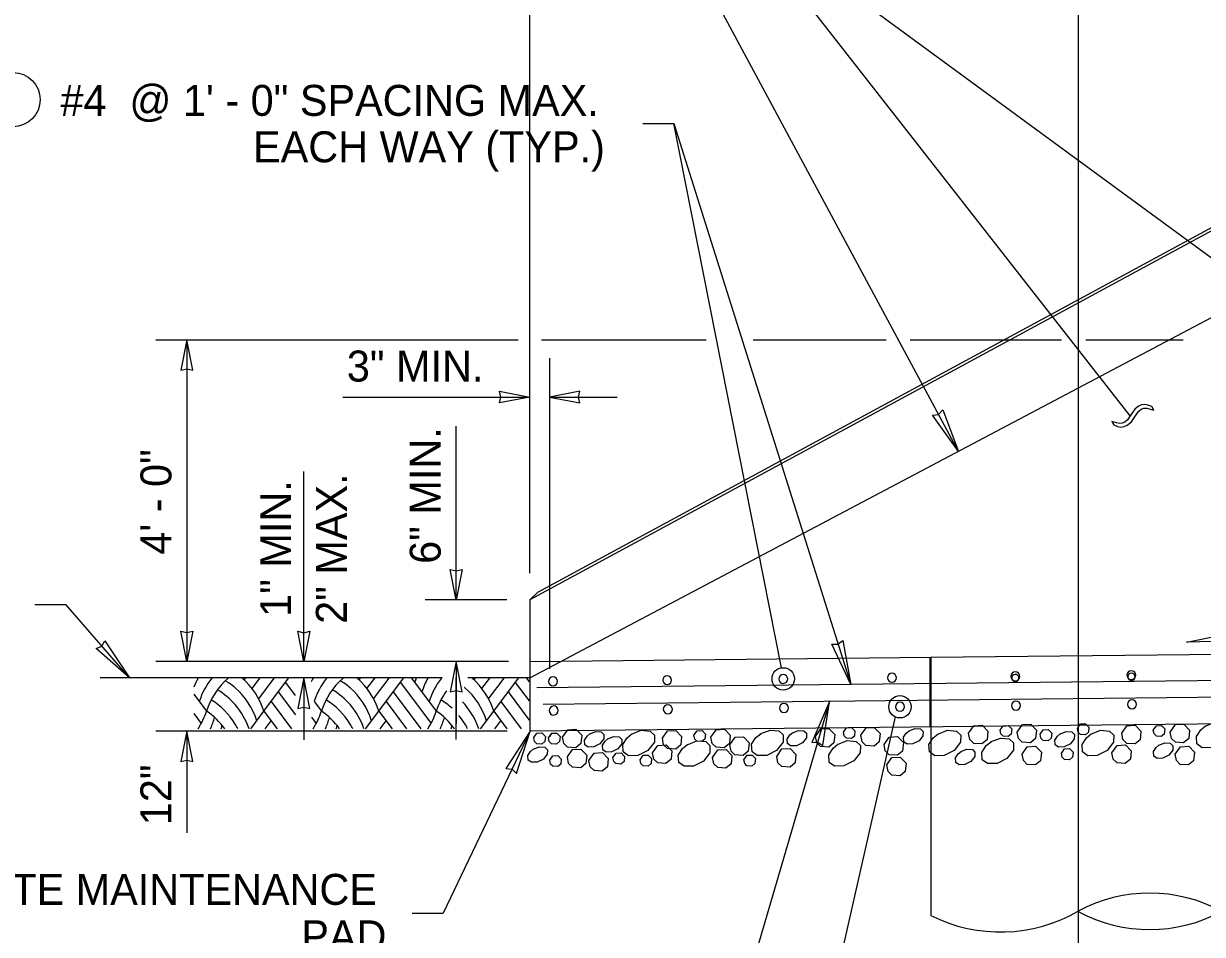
# Model space of a CAD drawing. Extents: x 99862 to 103680, y 99470 to 105076.
# Drawn here: x 101020 to 101629, y 100397 to 100868 of the extents above; entities that cross this region are included whole.
import ezdxf

# ---------------------------------------------------------------- set-up
doc = ezdxf.new("R2010")
doc.units = 0
for name, color, linetype in [('Level 1', 7, 'Continuous'), ('Level 12', 7, 'Continuous'), ('Level 15', 7, 'Continuous'), ('Level 16', 7, 'Continuous'), ('Level 2', 7, 'Continuous'), ('Level 20', 7, 'Continuous'), ('Level 3', 7, 'Continuous'), ('Level 31', 7, 'Continuous'), ('Level 32', 7, 'Continuous'), ('Level 33', 7, 'Continuous'), ('Level 6', 7, 'Continuous')]:
    doc.layers.add(name, color=color, linetype=linetype)

msp = doc.modelspace()

# ---------------------------------------------------------------- linework, layer by layer
at = {"layer": 'Level 1'}
for p in [(101822.22, 100863.19), (101285.51, 100574.36)]:
    msp.add_line(p, (101281.47, 100570.3), dxfattribs=at)
at = {"layer": 'Level 12'}
for p, q in [((101488.78, 100540.75), (101639.12, 100542.36)), ((101281.54, 100502.52), (101281.54, 100538.52)), ((101281.81, 100538.54), (101488.78, 100540.75)), ((101848.46, 100508.36), (101281.54, 100502.52))]:
    msp.add_line(p, q, dxfattribs=at)
at = {"layer": 'Level 15'}
for p, q in [((101281.45, 100747.06), (101281.45, 101114.77)), ((101591.84, 100665.55), (101385.61, 100928.99)), ((101820.5, 100609.84), (101385.61, 100928.99)), ((101565.13, 100284.95), (101565.13, 100883.5)), ((101503.03, 100647.03), (101377.78, 100879.78)), ((101339.87, 100816.5), (101355.87, 100816.5)), ((101355.87, 100816.5), (101447.34, 100526.68)), ((101411.56, 100535.3), (101355.87, 100816.5)), ((101281.45, 100584.16), (101281.45, 100747.06)), ((101088.15, 100704.75), (101275.45, 100704.75)), ((101104.15, 100704.75), (101104.15, 100538.54)), ((101287.45, 100704.75), (101333.49, 100704.75)), ((101333.49, 100704.75), (101372.66, 100704.75)), ((101396.88, 100704.75), (101465.68, 100704.75)), ((101477.99, 100704.75), (101556.24, 100704.75)), ((101568.86, 100704.75), (101619.14, 100704.75)), ((101291.55, 100695.2), (101291.55, 100534.75)), ((101184.7, 100675.2), (101281.45, 100675.2)), ((101291.58, 100675.2), (101326.63, 100675.2)), ((101596.04, 100670.5), (101594.11, 100668.95)), ((101597.57, 100671.14), (101596.04, 100670.5)), ((101599.17, 100671.32), (101597.57, 100671.14)), ((101600.93, 100671.05), (101599.17, 100671.32)), ((101602.95, 100670.3), (101600.93, 100671.05)), ((101604, 100668.47), (101602.95, 100670.3)), ((101591.84, 100665.55), (101590.38, 100663.46)), ((101594.11, 100668.95), (101591.84, 100665.55)), ((101592.38, 100662.31), (101594.9, 100665.93)), ((101594.9, 100665.93), (101596.28, 100667.92)), ((101596.28, 100667.92), (101597.44, 100668.87)), ((101597.44, 100668.87), (101598.78, 100669.35)), ((101598.78, 100669.35), (101600.43, 100669.4)), ((101600.43, 100669.4), (101604, 100668.47)), ((101243.34, 100570.3), (101243.34, 100660.18)), ((101584.62, 100661.83), (101582.31, 100662.57)), ((101582.31, 100662.57), (101583.37, 100660.74)), ((101583.37, 100660.74), (101585.2, 100659.98)), ((101586.33, 100661.56), (101584.62, 100661.83)), ((101585.2, 100659.98), (101586.97, 100659.69)), ((101587.69, 100661.71), (101586.33, 100661.56)), ((101586.97, 100659.69), (101588.67, 100659.88)), ((101588.92, 100662.21), (101587.69, 100661.71)), ((101588.67, 100659.88), (101590.29, 100660.56)), ((101590.38, 100663.46), (101588.92, 100662.21)), ((101590.29, 100660.56), (101592.38, 100662.31)), ((101164.6, 100538.54), (101164.6, 100636.66)), ((101025.57, 100567.91), (101041.57, 100567.91)), ((101074.42, 100529.98), (101041.57, 100567.91)), ((101269.47, 100570.3), (101227.34, 100570.3)), ((101180.08, 100538.54), (101088.15, 100538.54)), ((101270.45, 100538.54), (101180.08, 100538.54)), ((101243.34, 100538.54), (101243.34, 100506.54)), ((101164.6, 100529.98), (101164.6, 100497.98)), ((101243.34, 100498.22), (101243.34, 100530.22)), ((101436.33, 100517.79), (101385.25, 100343.71)), ((101470.26, 100509.87), (101416.69, 100274.32)), ((101269.63, 100502.52), (101088.15, 100502.52)), ((101104.15, 100502.52), (101104.15, 100449.95)), ((101281.54, 100502.52), (101236.61, 100408.46)), ((101220.61, 100408.46), (101236.61, 100408.46))]:
    msp.add_line(p, q, dxfattribs=at)
for points in [[(101104.15, 100704.75), (101101.07, 100689.03), (101104.15, 100689.76), (101107.24, 100689.03)], [(101281.45, 100675.2), (101265.73, 100672.12), (101266.46, 100675.2), (101265.73, 100678.29)], [(101291.58, 100675.2), (101307.31, 100672.12), (101306.58, 100675.2), (101307.31, 100678.29)], [(101503.03, 100647.03), (101489.6, 100665.73), (101492.73, 100666.22), (101494.86, 100668.56)], [(101243.34, 100570.3), (101240.26, 100586.02), (101243.34, 100585.3), (101246.43, 100586.02)], [(101104.15, 100538.54), (101101.07, 100554.26), (101104.15, 100553.53), (101107.24, 100554.26)], [(101164.6, 100538.41), (101161.51, 100554.13), (101164.6, 100553.4), (101167.68, 100554.13)], [(101074.42, 100529.98), (101057.22, 100545.28), (101060.17, 100546.44), (101061.73, 100549.19)], [(101447.34, 100526.68), (101437.55, 100547.52), (101440.72, 100547.42), (101443.24, 100549.34)], [(101243.34, 100538.54), (101240.26, 100522.81), (101243.34, 100523.54), (101246.43, 100522.81)], [(101164.6, 100529.98), (101161.51, 100514.25), (101164.6, 100514.98), (101167.68, 100514.25)], [(101436.34, 100517.8), (101427.17, 100496.68), (101430.33, 100496.88), (101432.91, 100495.04)], [(101104.15, 100502.52), (101101.07, 100486.79), (101104.15, 100487.52), (101107.24, 100486.79)], [(101281.54, 100502.52), (101269.07, 100483.16), (101272.22, 100482.84), (101274.47, 100480.6)]]:
    msp.add_lwpolyline(points, close=True, dxfattribs=at)
for centre in [(101412.42, 100529.51), (101472.76, 100515.09)]:
    msp.add_circle(centre, 5.78, dxfattribs=at)
at = {"layer": 'Level 16'}
for p, q in [((101488.78, 100540.75), (101488.78, 100407.24)), ((101564.9, 100515.67), (101564.9, 100515.67))]:
    msp.add_line(p, q, dxfattribs=at)
for centre, radius, start, end in [((101601.93, 100340.59), 78.19, 61.60047, 118.26803), ((101524.79, 100478.94), 80.23, 243.33243, 300), ((101601.93, 100478.15), 78.19, 241.73197, 298.39953)]:
    msp.add_arc(centre, radius, start, end, dxfattribs=at)
at = {"layer": 'Level 2'}
for p, q in [((101285.51, 100574.36), (101822.13, 100864.83)), ((101281.54, 100538.52), (101281.54, 100570.33))]:
    msp.add_line(p, q, dxfattribs=at)
at = {"layer": 'Level 20'}
msp.add_lwpolyline([(101759.94, 100551.99), (101620.9, 100548.45), (101673.82, 100559.17), (101669.68, 100551.57), (101759.89, 100553.87)], close=True, dxfattribs=at)
msp.add_circle((101014.29, 100828.91), 14, dxfattribs=at)
at = {"layer": 'Level 3'}
msp.add_line((101291.89, 100499.76), (101292.54, 100500.69), dxfattribs=at)
for points in [[(101508.24, 100501.46), (101510.93, 100505.29), (101515.22, 100505.53), (101518.21, 100502.44), (101517.77, 100498.1), (101515.12, 100495.9), (101510.88, 100496.2), (101508.89, 100498.14), (101508.24, 100501.46)], [(101524.55, 100503.04), (101526.17, 100505.33), (101528.74, 100505.48), (101530.54, 100503.62), (101530.28, 100501.02), (101528.69, 100499.7), (101526.14, 100499.88), (101524.94, 100501.04), (101524.56, 100503.03)], [(101533.37, 100502.04), (101536.06, 100505.87), (101540.35, 100506.11), (101543.33, 100503.02), (101542.9, 100498.68), (101540.25, 100496.48), (101536.01, 100496.78), (101534.02, 100498.72), (101533.37, 100502.04)], [(101564.49, 100503.92), (101566.1, 100506.21), (101568.68, 100506.36), (101570.47, 100504.5), (101570.21, 100501.9), (101568.62, 100500.58), (101566.07, 100500.76), (101564.88, 100501.92), (101564.49, 100503.92)], [(101587.39, 100501.46), (101590.08, 100505.29), (101594.37, 100505.53), (101597.35, 100502.44), (101596.92, 100498.1), (101594.27, 100495.9), (101590.03, 100496.2), (101588.04, 100498.14), (101587.39, 100501.46)], [(101603.7, 100503.04), (101605.32, 100505.33), (101607.89, 100505.48), (101609.68, 100503.62), (101609.42, 100501.02), (101607.83, 100499.7), (101605.29, 100499.88), (101604.09, 100501.04), (101603.7, 100503.03)], [(101612.52, 100502.04), (101615.2, 100505.87), (101619.5, 100506.11), (101622.48, 100503.02), (101622.05, 100498.68), (101619.4, 100496.48), (101615.16, 100496.78), (101613.16, 100498.72), (101612.52, 100502.04)], [(101630.56, 100505.1), (101635.59, 100507.1), (101640.21, 100506.7), (101642.41, 100504.61), (101642.34, 100500.86), (101639.01, 100496.6), (101633.85, 100494.02), (101629, 100493.94), (101626.27, 100495.88), (101626.01, 100499.75), (101628.22, 100503.21), (101630.76, 100505.23)], [(101283.51, 100499.16), (101285.13, 100501.45), (101287.7, 100501.6), (101289.5, 100499.74), (101289.24, 100497.14), (101287.65, 100495.82), (101285.1, 100496), (101283.9, 100497.16), (101283.52, 100499.16)], [(101291.12, 100499.09), (101292.73, 100501.39), (101295.31, 100501.53), (101297.1, 100499.68), (101296.84, 100497.08), (101295.25, 100495.75), (101292.71, 100495.94), (101291.51, 100497.1), (101291.12, 100499.09)], [(101298.3, 100499.42), (101300.99, 100503.24), (101305.28, 100503.49), (101308.26, 100500.39), (101307.83, 100496.06), (101305.18, 100493.85), (101300.94, 100494.16), (101298.95, 100496.09), (101298.3, 100499.42)], [(101312.47, 100501.14), (101315.54, 100502.36), (101318.37, 100502.11), (101319.71, 100500.84), (101319.67, 100498.54), (101317.63, 100495.94), (101314.48, 100494.36), (101311.51, 100494.31), (101309.84, 100495.5), (101309.68, 100497.86), (101311.04, 100499.98), (101312.59, 100501.22)], [(101321.76, 100498.54), (101324.84, 100499.76), (101327.66, 100499.51), (101329, 100498.23), (101328.96, 100495.94), (101326.92, 100493.34), (101323.77, 100491.76), (101320.81, 100491.71), (101319.13, 100492.9), (101318.98, 100495.26), (101320.33, 100497.38), (101321.88, 100498.62)], [(101334.01, 100500.97), (101339.04, 100502.97), (101343.66, 100502.57), (101345.86, 100500.48), (101345.79, 100496.73), (101342.45, 100492.47), (101337.3, 100489.89), (101332.45, 100489.81), (101329.72, 100491.75), (101329.46, 100495.62), (101331.67, 100499.08), (101334.21, 100501.1)], [(101349.94, 100498.83), (101352.63, 100502.66), (101356.92, 100502.91), (101359.91, 100499.81), (101359.48, 100495.47), (101356.83, 100493.27), (101352.59, 100493.58), (101350.59, 100495.51), (101349.94, 100498.83)], [(101366.26, 100500.41), (101367.87, 100502.7), (101370.45, 100502.85), (101372.24, 100500.99), (101371.98, 100498.39), (101370.39, 100497.07), (101367.84, 100497.25), (101366.65, 100498.41), (101366.26, 100500.41)], [(101375.07, 100499.42), (101377.76, 100503.24), (101382.05, 100503.49), (101385.04, 100500.39), (101384.61, 100496.06), (101381.95, 100493.85), (101377.72, 100494.16), (101375.72, 100496.09), (101375.07, 100499.42)], [(101384.83, 100495.48), (101387.52, 100499.31), (101391.81, 100499.55), (101394.8, 100496.46), (101394.36, 100492.12), (101391.71, 100489.91), (101387.47, 100490.22), (101385.48, 100492.16), (101384.83, 100495.48)], [(101400.57, 100501.07), (101405.61, 100503.06), (101410.23, 100502.67), (101412.42, 100500.58), (101412.35, 100496.83), (101409.02, 100492.57), (101403.87, 100489.99), (101399.01, 100489.91), (101396.28, 100491.85), (101396.02, 100495.71), (101398.24, 100499.17), (101400.78, 100501.2)], [(101417.21, 100501.7), (101420.29, 100502.92), (101423.11, 100502.68), (101424.46, 100501.4), (101424.41, 100499.11), (101422.37, 100496.5), (101419.23, 100494.93), (101416.26, 100494.88), (101414.59, 100496.06), (101414.43, 100498.43), (101415.78, 100500.54), (101417.34, 100501.78)], [(101429.09, 100499.8), (101431.78, 100503.63), (101436.07, 100503.87), (101439.06, 100500.78), (101438.63, 100496.44), (101435.97, 100494.23), (101431.73, 100494.54), (101429.74, 100496.48), (101429.09, 100499.8)], [(101443.51, 100502), (101445.12, 100504.29), (101447.7, 100504.44), (101449.49, 100502.58), (101449.23, 100499.98), (101447.64, 100498.66), (101445.09, 100498.84), (101443.9, 100500), (101443.51, 100502)], [(101452.53, 100500.36), (101455.22, 100504.19), (101459.51, 100504.43), (101462.49, 100501.34), (101462.06, 100497), (101459.41, 100494.8), (101455.17, 100495.1), (101453.18, 100497.04), (101452.53, 100500.36)], [(101464.54, 100495.59), (101467.23, 100499.42), (101471.53, 100499.66), (101474.51, 100496.57), (101474.08, 100492.23), (101471.43, 100490.03), (101467.19, 100490.33), (101465.19, 100492.27), (101464.55, 100495.59)], [(101477.45, 100502.66), (101480.52, 100503.88), (101483.35, 100503.64), (101484.69, 100502.36), (101484.65, 100500.07), (101482.61, 100497.46), (101479.46, 100495.89), (101476.49, 100495.84), (101474.82, 100497.03), (101474.66, 100499.39), (101476.02, 100501.51), (101477.57, 100502.74)], [(101492.31, 100500.97), (101497.34, 100502.97), (101501.96, 100502.57), (101504.15, 100500.48), (101504.08, 100496.73), (101500.75, 100492.47), (101495.6, 100489.89), (101490.74, 100489.81), (101488.01, 100491.75), (101487.75, 100495.62), (101489.97, 100499.08), (101492.51, 100501.1)], [(101545.23, 100500.88), (101546.84, 100503.18), (101549.42, 100503.32), (101551.21, 100501.47), (101550.95, 100498.86), (101549.36, 100497.54), (101546.81, 100497.72), (101545.62, 100498.89), (101545.23, 100500.88)], [(101555.68, 100501.14), (101558.76, 100502.36), (101561.59, 100502.11), (101562.93, 100500.84), (101562.89, 100498.54), (101560.85, 100495.94), (101557.7, 100494.36), (101554.73, 100494.31), (101553.06, 100495.5), (101552.9, 100497.86), (101554.26, 100499.98), (101555.81, 100501.22)], [(101571.45, 100500.97), (101576.48, 100502.97), (101581.11, 100502.57), (101583.3, 100500.48), (101583.23, 100496.73), (101579.9, 100492.47), (101574.75, 100489.89), (101569.89, 100489.81), (101567.16, 100491.75), (101566.9, 100495.62), (101569.12, 100499.08), (101571.66, 100501.1)], [(101283.27, 100493.22), (101286.34, 100494.44), (101289.17, 100494.2), (101290.51, 100492.92), (101290.47, 100490.63), (101288.43, 100488.02), (101285.28, 100486.45), (101282.31, 100486.4), (101280.64, 100487.58), (101280.48, 100489.95), (101281.84, 100492.06), (101283.39, 100493.3)], [(101300.85, 100489.15), (101303.54, 100492.98), (101307.83, 100493.22), (101310.82, 100490.13), (101310.39, 100485.79), (101307.73, 100483.59), (101303.5, 100483.89), (101301.5, 100485.83), (101300.85, 100489.15)], [(101344.88, 100491.34), (101347.57, 100495.17), (101351.86, 100495.41), (101354.85, 100492.32), (101354.42, 100487.98), (101351.77, 100485.78), (101347.53, 100486.08), (101345.53, 100488.02), (101344.88, 100491.34)], [(101362.69, 100495.5), (101367.72, 100497.5), (101372.35, 100497.1), (101374.54, 100495.01), (101374.47, 100491.26), (101371.14, 100487), (101365.99, 100484.42), (101361.13, 100484.34), (101358.4, 100486.28), (101358.14, 100490.15), (101360.36, 100493.61), (101362.9, 100495.63)], [(101409.05, 100489.45), (101411.73, 100493.28), (101416.03, 100493.52), (101419.01, 100490.43), (101418.58, 100486.09), (101415.93, 100483.89), (101411.69, 100484.19), (101409.7, 100486.13), (101409.05, 100489.45)], [(101440.49, 100495.59), (101445.52, 100497.59), (101450.14, 100497.19), (101452.34, 100495.1), (101452.27, 100491.35), (101448.93, 100487.09), (101443.78, 100484.51), (101438.93, 100484.43), (101436.19, 100486.37), (101435.93, 100490.24), (101438.15, 100493.69), (101440.69, 100495.72)], [(101504.28, 100491.99), (101507.36, 100493.21), (101510.18, 100492.97), (101511.53, 100491.69), (101511.48, 100489.4), (101509.44, 100486.79), (101506.3, 100485.22), (101503.33, 100485.16), (101501.66, 100486.35), (101501.5, 100488.72), (101502.85, 100490.83), (101504.41, 100492.07)], [(101519.64, 100496.91), (101524.67, 100498.9), (101529.29, 100498.5), (101531.48, 100496.41), (101531.41, 100492.66), (101528.08, 100488.4), (101522.93, 100485.83), (101518.07, 100485.74), (101515.34, 100487.68), (101515.08, 100491.55), (101517.3, 100495.01), (101519.84, 100497.03)], [(101535.9, 100490.59), (101538.59, 100494.42), (101542.88, 100494.66), (101545.86, 100491.57), (101545.43, 100487.23), (101542.78, 100485.03), (101538.54, 100485.33), (101536.55, 100487.27), (101535.9, 100490.59)], [(101556.28, 100491.02), (101557.9, 100493.31), (101560.47, 100493.46), (101562.27, 100491.6), (101562.01, 100489), (101560.42, 100487.68), (101557.87, 100487.86), (101556.67, 100489.02), (101556.29, 100491.02)], [(101582.33, 100491.34), (101585.02, 100495.17), (101589.31, 100495.41), (101592.29, 100492.32), (101591.86, 100487.98), (101589.21, 100485.78), (101584.97, 100486.08), (101582.98, 100488.02), (101582.33, 100491.34)], [(101606.6, 100495.27), (101609.67, 100496.49), (101612.5, 100496.25), (101613.84, 100494.97), (101613.8, 100492.68), (101611.76, 100490.07), (101608.61, 100488.5), (101605.64, 100488.45), (101603.97, 100489.63), (101603.81, 100492), (101605.17, 100494.11), (101606.72, 100495.35)], [(101615.05, 100490.59), (101617.73, 100494.42), (101622.03, 100494.66), (101625.01, 100491.57), (101624.58, 100487.23), (101621.93, 100485.03), (101617.69, 100485.33), (101615.7, 100487.27), (101615.05, 100490.59)], [(101291.69, 100487.49), (101293.31, 100489.78), (101295.88, 100489.93), (101297.67, 100488.07), (101297.41, 100485.47), (101295.82, 100484.15), (101293.28, 100484.33), (101292.08, 100485.49), (101291.69, 100487.48)], [(101311.96, 100487.35), (101314.65, 100491.17), (101318.94, 100491.42), (101321.93, 100488.32), (101321.5, 100483.99), (101318.84, 100481.78), (101314.61, 100482.09), (101312.61, 100484.02), (101311.96, 100487.35)], [(101324.38, 100488.86), (101326, 100491.16), (101328.57, 100491.3), (101330.36, 100489.45), (101330.11, 100486.84), (101328.51, 100485.52), (101325.97, 100485.7), (101324.77, 100486.87), (101324.39, 100488.86)], [(101338.42, 100487.71), (101340.04, 100490.01), (101342.61, 100490.16), (101344.4, 100488.3), (101344.14, 100485.7), (101342.55, 100484.37), (101340.01, 100484.56), (101338.81, 100485.72), (101338.42, 100487.71)], [(101375.9, 100488.97), (101378.59, 100492.8), (101382.88, 100493.04), (101385.87, 100489.95), (101385.44, 100485.61), (101382.78, 100483.41), (101378.55, 100483.71), (101376.55, 100485.65), (101375.9, 100488.97)], [(101392.1, 100487.71), (101393.71, 100490.01), (101396.29, 100490.16), (101398.08, 100488.3), (101397.82, 100485.7), (101396.23, 100484.37), (101393.69, 100484.56), (101392.49, 100485.72), (101392.1, 100487.71)], [(101465.95, 100485.03), (101468.64, 100488.85), (101472.93, 100489.1), (101475.91, 100486), (101475.48, 100481.67), (101472.83, 100479.46), (101468.59, 100479.77), (101466.6, 100481.7), (101465.95, 100485.02)]]:
    msp.add_lwpolyline(points, dxfattribs=at)
at = {"layer": 'Level 31'}
for centre, start, end in [((101532.76, 100515.73), 90.61251, 270.61251), ((101532.76, 100515.73), 270.61251, 90.61251), ((101592.75, 100516.37), 90.61251, 270.61251), ((101592.75, 100516.37), 270.61251, 90.61251), ((101293.76, 100513.17), 90.61251, 270.61251), ((101293.76, 100513.17), 270.61251, 90.61251), ((101352.77, 100513.81), 90.61251, 270.61251), ((101352.77, 100513.81), 270.61251, 90.61251), ((101412.76, 100514.45), 90.61251, 270.61251), ((101412.76, 100514.45), 270.61251, 90.61251), ((101472.76, 100515.09), 90.61251, 270.61251), ((101472.76, 100515.09), 270.61251, 90.61251)]:
    msp.add_arc(centre, 2.34, start, end, dxfattribs=at)
at = {"layer": 'Level 32'}
msp.add_line((101829.61, 100522), (101288.39, 100516.21), dxfattribs=at)
at = {"layer": 'Level 33'}
for p, q in [((101488.28, 100540.64), (101488.28, 100504.68)), ((101826.21, 100530.61), (101284.99, 100524.82))]:
    msp.add_line(p, q, dxfattribs=at)
for centre, radius, start, end in [((101293.42, 100528.23), 2.3, 90.61251, 270.61251), ((101293.42, 100528.23), 2.3, 270.61251, 90.61251), ((101352.42, 100528.87), 2.3, 90.61251, 270.61251), ((101352.42, 100528.87), 2.3, 270.61251, 90.61251), ((101412.42, 100529.51), 2.3, 90.61251, 270.61251), ((101412.42, 100529.51), 2.3, 270.61251, 90.61251), ((101468.6, 100530.15), 2.3, 90.61251, 270.61251), ((101468.6, 100530.15), 2.3, 270.61251, 90.61251), ((101532.41, 100530.8), 2.3, 90.61251, 270.61251), ((101532.41, 100529.97), 1.88, 90.61251, 270.61251), ((101532.41, 100530.8), 2.3, 270.61251, 90.61251), ((101532.41, 100529.97), 1.88, 270.61251, 90.61251), ((101592.41, 100531.44), 2.3, 90.61251, 270.61251), ((101592.41, 100530.61), 1.88, 90.61251, 270.61251), ((101592.41, 100531.44), 2.3, 270.61251, 90.61251), ((101592.41, 100530.61), 1.88, 270.61251, 90.61251)]:
    msp.add_arc(centre, radius, start, end, dxfattribs=at)
at = {"layer": 'Level 6'}
for p, q in [((101848.36, 100829.62), (101281.64, 100529.98)), ((101236.16, 100529.98), (101059.35, 100529.98)), ((101133.78, 100528.97), (101134.46, 100529.87)), ((101137.85, 100524.5), (101141.88, 100529.87)), ((101141.3, 100519.2), (101149.31, 100529.87)), ((101143.97, 100512.86), (101156.73, 100529.87)), ((101193.17, 100528.97), (101193.85, 100529.87)), ((101197.25, 100524.5), (101201.28, 100529.87)), ((101200.7, 100519.2), (101208.7, 100529.87)), ((101203.37, 100512.86), (101216.13, 100529.87)), ((101220.31, 100529.87), (101233.07, 100512.86)), ((101281.64, 100529.98), (101249.34, 100529.98)), ((101252.57, 100528.97), (101253.25, 100529.87)), ((101256.65, 100524.5), (101260.68, 100529.87)), ((101260.09, 100519.2), (101268.1, 100529.87)), ((101262.77, 100512.86), (101275.53, 100529.87)), ((101279.71, 100529.87), (101281.11, 100528)), ((101155.11, 100527.71), (101160.14, 100521)), ((101214.51, 100527.71), (101230.39, 100506.53)), ((101273.9, 100527.71), (101281.11, 100518.1)), ((101107.73, 100521.58), (101114.27, 100512.86)), ((101147.68, 100517.81), (101158.22, 100503.77)), ((101151.4, 100522.76), (101160.25, 100510.96)), ((101169.93, 100517.85), (101173.67, 100512.86)), ((101207.08, 100517.81), (101217.61, 100503.77)), ((101210.79, 100522.76), (101225.04, 100503.77)), ((101266.48, 100517.81), (101277.01, 100503.77)), ((101270.19, 100522.76), (101281.11, 100508.2)), ((101107.73, 100511.68), (101111.6, 100506.53)), ((101137.15, 100503.77), (101143.97, 100512.86)), ((101143.97, 100512.86), (101150.79, 100503.77)), ((101196.55, 100503.77), (101203.37, 100512.86)), ((101203.37, 100512.86), (101210.19, 100503.77)), ((101255.95, 100503.77), (101262.77, 100512.86)), ((101262.77, 100512.86), (101269.58, 100503.77)), ((101144.58, 100503.77), (101147.68, 100507.91)), ((101168.65, 100509.66), (101171, 100506.53)), ((101203.98, 100503.77), (101207.08, 100507.91)), ((101263.37, 100503.77), (101266.48, 100507.91))]:
    msp.add_line(p, q, dxfattribs=at)
for centre, start, end in [((101142.66, 100511.37), 150.50505, 158.34455), ((101146.37, 100506.42), 141.38617, 162.3566), ((101150.08, 100501.47), 130.9056, 162.3566), ((101108.16, 100501.47), 17.6434, 49.0944), ((101202.06, 100511.37), 150.50505, 153.4805), ((101205.77, 100506.42), 141.38617, 162.3566), ((101209.48, 100501.47), 130.9056, 162.3566), ((101167.56, 100501.47), 17.6434, 49.0944), ((101257.74, 100516.32), 158.86138, 162.3566), ((101261.45, 100511.37), 150.50505, 162.3566), ((101265.17, 100506.42), 141.38617, 162.3566), ((101226.96, 100501.47), 17.6434, 49.0944), ((101100.74, 100491.57), 40.94134, 59.30215), ((101104.45, 100496.52), 48.95968, 58.54646), ((101104.45, 100496.52), 17.6434, 48.95975), ((101160.14, 100491.57), 40.94134, 59.30215), ((101163.85, 100496.52), 48.95968, 58.54646), ((101163.85, 100496.52), 17.6434, 48.95975), ((101223.24, 100496.52), 48.95968, 49.55103), ((101223.24, 100496.52), 17.6434, 48.95975), ((101097.03, 100486.62), 31.33163, 58.48737), ((101156.42, 100486.62), 31.33163, 58.48737), ((101268.88, 100501.47), 144.34512, 162.3566), ((101215.82, 100486.62), 47.44053, 58.48737), ((101219.53, 100491.57), 40.94134, 43.82968), ((101078.46, 100524.25), 326.97404, 342.3566), ((101093.31, 100481.67), 36.01876, 56.09639), ((101100.74, 100491.57), 18.9418, 40.94141), ((101137.86, 100524.25), 326.97404, 342.3566), ((101152.71, 100481.67), 36.01876, 56.09639), ((101160.14, 100491.57), 18.9418, 40.94141), ((101197.26, 100524.25), 326.97404, 342.3566), ((101212.11, 100481.67), 36.01876, 56.09639), ((101219.53, 100491.57), 18.9418, 40.94141), ((101082.18, 100519.3), 335.58785, 345.01126), ((101085.89, 100514.35), 343.6457, 346.31988), ((101097.03, 100486.62), 27.15046, 31.33172), ((101141.57, 100519.3), 335.58785, 345.01126), ((101145.29, 100514.35), 343.6457, 346.31988), ((101156.42, 100486.62), 27.15046, 31.33172), ((101200.97, 100519.3), 335.58785, 345.01126), ((101204.68, 100514.35), 343.6457, 346.31988), ((101215.82, 100486.62), 31.33163, 39.59994), ((101215.82, 100486.62), 27.15046, 31.33172)]:
    msp.add_arc(centre, 37.58, start, end, dxfattribs=at)

# ---------------------------------------------------------------- texts
at = {"layer": 'Level 20'}
for s, p in [(' #4  @ 1\' - 0" SPACING MAX.', (101032.82, 100820.5)), (' EACH WAY (TYP.)', (101132.43, 100796.5)), ('3" MIN.', (101186.84, 100683.2)), ('CONCRETE MAINTENANCE ', (100920.67, 100412.73)), ('PAD', (101163.32, 100388.73))]:
    msp.add_text(s, height=16, dxfattribs=at).set_placement(p)
for s, p in [('6" MIN.', (101235.34, 100588.96)), ('4\' - 0"', (101096.15, 100593.71)), ('2" MAX.', (101186.84, 100557.95)), ('1" MIN.', (101158.04, 100561.58)), ('12"', (101096.15, 100453.89))]:
    msp.add_text(s, height=16, rotation=90, dxfattribs=at).set_placement(p)

doc.saveas('drawing.dxf')
